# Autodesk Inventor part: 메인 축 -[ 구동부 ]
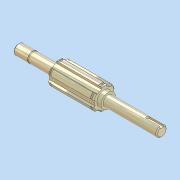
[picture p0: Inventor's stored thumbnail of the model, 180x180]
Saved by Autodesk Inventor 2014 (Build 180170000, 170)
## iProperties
Created: 2012-05
Part Number: 메인 축 -[ 구동부 ]
Document SubType Name: 모델링
Designer: SeoGD™
Mass: 21.4462 g
Surface Area: 72.5109 cm^2
Volume: 21.4462 cm^3
Density: 1 g/cm^3
Material: 강철, 연강
Appearance: 강철
변환 표준: STEP AP214IS
파일 이름: C:\Users\SeoGD\Desktop\?쒗뿕\硫붿씤 異?.stp
전처리기: Build: 253, Release: 2010 SP1 - Date: Wed 07/29/2009
전송 단위: 밀리미터
불확실성: 0.01
Author: SeoGD™
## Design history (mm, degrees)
sketch "스케치1"
  geometry: L1 (-69.5, 0)-(69.5, 0); L2 (69.5, 0)-(69.5, 5); L3 (69.5, 5)-(55.5, 5); L4 (55.5, 5)-(55.5, 4.8); L5 (55.5, 4.8)-(54.35, 4.8); L6 (54.35, 4.8)-(54.35, 5); L7 (54.35, 5)-(30.5, 5); L8 (30.5, 5)-(30.5, 9); L9 (30.5, 9)-(-13.5, 9); L10 (-13.5, 9)-(-13.5, 7); L11 (-13.5, 7)-(-17.5, 7); L12 (-17.5, 7)-(-17.5, 5); L13 (-17.5, 5)-(-69.5, 5); L14 (-69.5, 5)-(-69.5, 0); 2 further points
  constraints: 28 end point, 9 parallel, 4 collinear, 2 perpendicular, 1 coincident, 1 horizontal, 1 midpoint
  dimensions: "d2" = 1.15 distance between parallel lines of L6 L4; "d3" = 10 diameter of L3 L1; "d4" = 9.6 diameter of L5 L1; "d6" = 44 distance between parallel lines of L10 L8; "d7" = 4 distance between parallel lines of L12 L10; "d8" = 14 diameter of L11 L1; "d9" = 18 diameter of L9 L1; "d33" = 52 distance from line of L12.end L14; "d37" = 39 distance between parallel lines of L8 L2; "d38" = 14 distance between parallel lines of L2 L4
revolve "회전1" sketch "스케치1" stored, may be unused: angle "d10" = 90 deg
sketch "스케치2"
  geometry: L1 (2.5, 10.712)-(2.5, 8.646); L2 (-2.5, 10.712)-(-2.5, 8.646); A1 r 9 centre (0, 0) between (2.5, 8.646) and (-2.5, 8.646) reference; A2 r 11 centre (0, 0) between (2.5, 10.712) and (-2.5, 10.712); 1 further point
  constraints: 4 end point, 4 point on circle, 2 parallel, 1 centre point, 1 coincident, 1 vertical
  dimensions: "d11" = 22 diameter of A2; "d12" = 5 distance between parallel lines of L1 L2
extrude "돌출1" join sketch "스케치2" stored distance "d13" = 10; taper "d14" = 0 deg
chamfer "모따기1" distance "d15" = 1; stored, may be unused: second distance "d16" = 2, angle "d17" = 45 deg
node "작업 평면1"
node "작업 평면2"
sketch "스케치3"
  geometry: L1 (2.5, 10.712)-(2.5, 10.198); L2 (-2.5, 10.712)-(-2.5, 10.198); A1 r 11 centre (0, 0) between (2.5, 10.712) and (-2.5, 10.712) reference; A2 r 10.5 centre (0, 0) between (2.5, 10.198) and (-2.5, 10.198); 1 further point
  constraints: 4 end point, 2 point on circle, 1 centre point, 1 coincident, 1 parallel, 1 vertical
  dimensions: "d19" = 21 diameter of A2
extrude "돌출2" cut sketch "스케치3" distance "d20" = 1.35; taper "d21" = 0 deg
node "작업 평면3"
sketch "스케치4"
  geometry: L1 (-26, -5)-(-26, 5) reference; L2 (-26, 1.5)-(-12.5, 1.5); L3 (-12.5, -1.5)-(-26, -1.5); A1 r 1.5 centre (-12.5, 0) between (-12.5, -1.5) and (-12.5, 1.5); 2 further points
  constraints: 4 end point, 2 perpendicular, 2 point on circle, 2 point on line, 2 tangent, 1 centre point, 1 horizontal alignment, 1 midpoint
  dimensions: "d25" = 3 distance between parallel lines of L3 L2; "d26" = 15 dimension on A1 L1
extrude "돌출3" cut sketch "스케치4" distance "d27" = 1.8; taper "d28" = 0 deg
chamfer "모따기2" distance "d29" = 1; stored, may be unused: second distance "d30" = 2, angle "d31" = 45 deg
node "솔리드1"
node "솔리드 본체"
node "곡면 본체"
mirror "대칭1"
pattern_circular "원형 패턴1" dims "d23" = 360 deg
node "솔리드2"
other parameters: "d18" = -1.65
